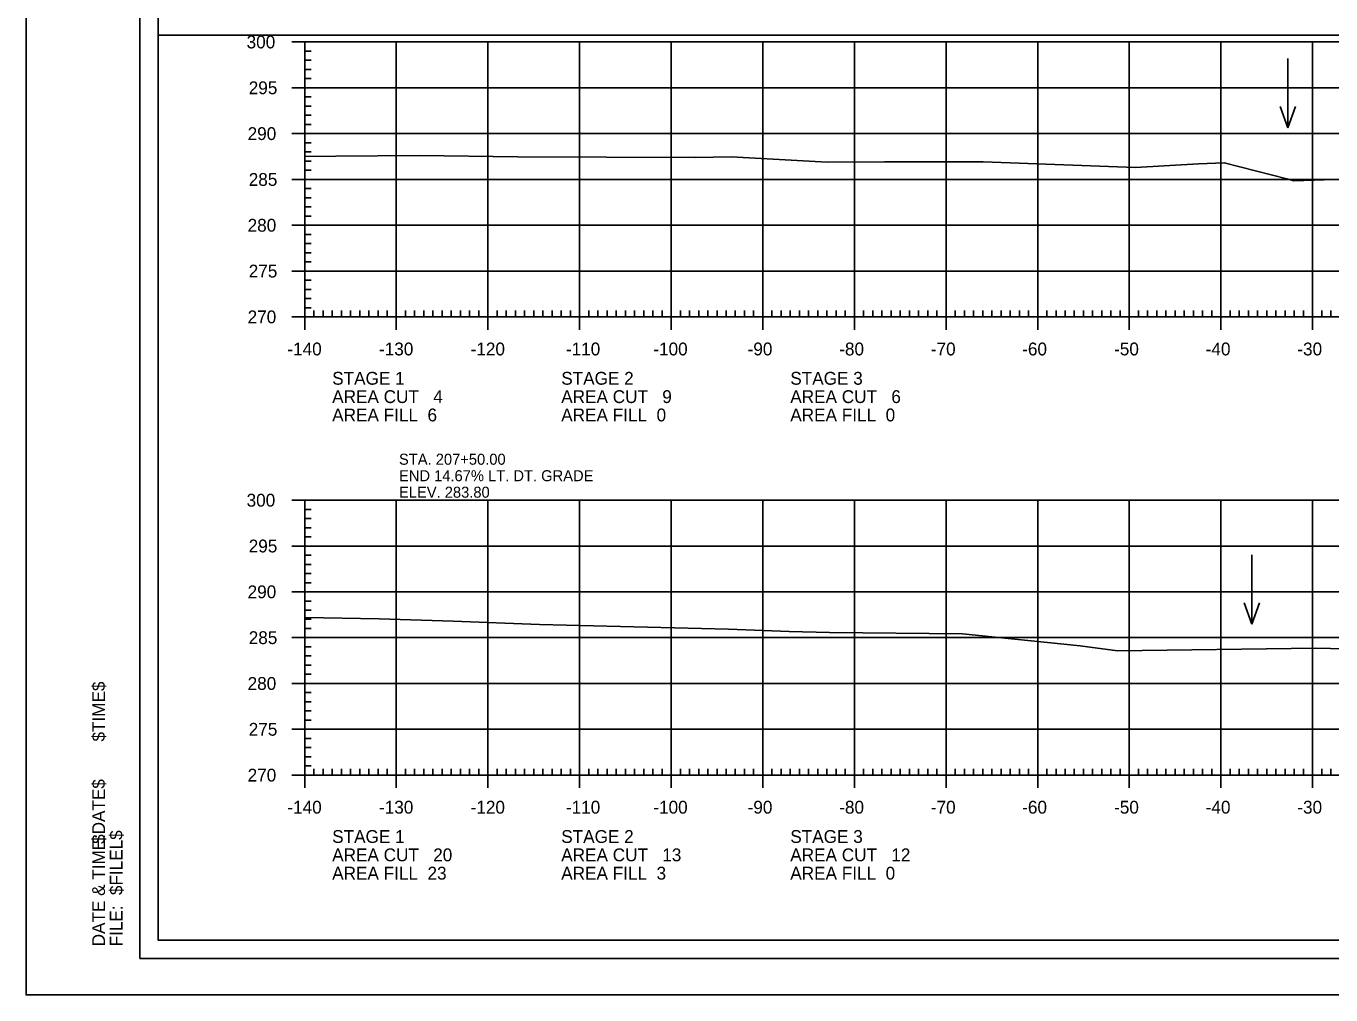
# Model space of a CAD drawing. Extents: x 1368713 to 1370673, y 380279 to 380950.
# Drawn here: x 1370339.2 to 1370481.6, y 380737.1 to 380842.8 of the extents above; entities that cross this region are included whole.
import ezdxf

# ---------------------------------------------------------------- set-up
doc = ezdxf.new("R2010")
doc.units = 0
for name, color, linetype in [('Notes', 7, 'Continuous'), ('R_Axis', 7, 'Continuous'), ('R_Axis Annot', 7, 'Continuous'), ('R_Border', 7, 'Continuous'), ('R_Border Notes', 7, 'Continuous'), ('R_Exist Surface', 7, 'Continuous'), ('R_Grid', 7, 'Continuous'), ('R_No Plot', 7, 'Continuous'), ('R_Water Annot', 7, 'Continuous')]:
    doc.layers.add(name, color=color, linetype=linetype)

msp = doc.modelspace()

# ---------------------------------------------------------------- linework, layer by layer
at = {"layer": 'R_Axis'}
for p, q in [((1370368.23, 380841.09), (1370371.03, 380841.09)), ((1370369.63, 380811.09), (1370369.63, 380841.09)), ((1370369.63, 380840.09), (1370370.33, 380840.09)), ((1370369.63, 380839.09), (1370370.33, 380839.09)), ((1370369.63, 380838.09), (1370370.33, 380838.09)), ((1370369.63, 380837.09), (1370370.33, 380837.09)), ((1370368.23, 380836.09), (1370371.03, 380836.09)), ((1370369.63, 380835.09), (1370370.33, 380835.09)), ((1370369.63, 380834.09), (1370370.33, 380834.09)), ((1370369.63, 380833.09), (1370370.33, 380833.09)), ((1370368.23, 380831.09), (1370371.03, 380831.09)), ((1370369.63, 380832.09), (1370370.33, 380832.09)), ((1370369.63, 380830.09), (1370370.33, 380830.09)), ((1370369.63, 380829.09), (1370370.33, 380829.09)), ((1370369.63, 380828.09), (1370370.33, 380828.09)), ((1370369.63, 380827.09), (1370370.33, 380827.09)), ((1370368.23, 380826.09), (1370371.03, 380826.09)), ((1370369.63, 380825.09), (1370370.33, 380825.09)), ((1370369.63, 380824.09), (1370370.33, 380824.09)), ((1370369.63, 380823.09), (1370370.33, 380823.09)), ((1370368.23, 380821.09), (1370371.03, 380821.09)), ((1370369.63, 380822.09), (1370370.33, 380822.09)), ((1370369.63, 380820.09), (1370370.33, 380820.09)), ((1370369.63, 380819.09), (1370370.33, 380819.09)), ((1370369.63, 380818.09), (1370370.33, 380818.09)), ((1370369.63, 380817.09), (1370370.33, 380817.09)), ((1370368.23, 380816.09), (1370371.03, 380816.09)), ((1370369.63, 380815.09), (1370370.33, 380815.09)), ((1370369.63, 380814.09), (1370370.33, 380814.09)), ((1370369.63, 380813.09), (1370370.33, 380813.09)), ((1370369.63, 380809.69), (1370369.63, 380812.49)), ((1370379.63, 380809.69), (1370379.63, 380812.49)), ((1370389.63, 380809.69), (1370389.63, 380812.49)), ((1370399.63, 380809.69), (1370399.63, 380812.49)), ((1370409.63, 380809.69), (1370409.63, 380812.49)), ((1370419.63, 380809.69), (1370419.63, 380812.49)), ((1370429.63, 380809.69), (1370429.63, 380812.49)), ((1370439.63, 380809.69), (1370439.63, 380812.49)), ((1370449.63, 380809.69), (1370449.63, 380812.49)), ((1370459.63, 380809.69), (1370459.63, 380812.49)), ((1370469.63, 380809.69), (1370469.63, 380812.49)), ((1370479.63, 380809.69), (1370479.63, 380812.49)), ((1370368.23, 380811.09), (1370371.03, 380811.09)), ((1370369.63, 380812.09), (1370370.33, 380812.09)), ((1370369.63, 380811.09), (1370649.63, 380811.09)), ((1370370.63, 380811.09), (1370370.63, 380811.79)), ((1370371.63, 380811.09), (1370371.63, 380811.79)), ((1370372.63, 380811.09), (1370372.63, 380811.79)), ((1370373.63, 380811.09), (1370373.63, 380811.79)), ((1370374.63, 380811.09), (1370374.63, 380811.79)), ((1370375.63, 380811.09), (1370375.63, 380811.79)), ((1370376.63, 380811.09), (1370376.63, 380811.79)), ((1370377.63, 380811.09), (1370377.63, 380811.79)), ((1370378.63, 380811.09), (1370378.63, 380811.79)), ((1370380.63, 380811.09), (1370380.63, 380811.79)), ((1370381.63, 380811.09), (1370381.63, 380811.79)), ((1370382.63, 380811.09), (1370382.63, 380811.79)), ((1370383.63, 380811.09), (1370383.63, 380811.79)), ((1370384.63, 380811.09), (1370384.63, 380811.79)), ((1370385.63, 380811.09), (1370385.63, 380811.79)), ((1370386.63, 380811.09), (1370386.63, 380811.79)), ((1370387.63, 380811.09), (1370387.63, 380811.79)), ((1370388.63, 380811.09), (1370388.63, 380811.79)), ((1370390.63, 380811.09), (1370390.63, 380811.79)), ((1370391.63, 380811.09), (1370391.63, 380811.79)), ((1370392.63, 380811.09), (1370392.63, 380811.79)), ((1370393.63, 380811.09), (1370393.63, 380811.79)), ((1370394.63, 380811.09), (1370394.63, 380811.79)), ((1370395.63, 380811.09), (1370395.63, 380811.79)), ((1370396.63, 380811.09), (1370396.63, 380811.79)), ((1370397.63, 380811.09), (1370397.63, 380811.79)), ((1370398.63, 380811.09), (1370398.63, 380811.79)), ((1370400.63, 380811.09), (1370400.63, 380811.79)), ((1370401.63, 380811.09), (1370401.63, 380811.79)), ((1370402.63, 380811.09), (1370402.63, 380811.79)), ((1370403.63, 380811.09), (1370403.63, 380811.79)), ((1370404.63, 380811.09), (1370404.63, 380811.79)), ((1370405.63, 380811.09), (1370405.63, 380811.79)), ((1370406.63, 380811.09), (1370406.63, 380811.79)), ((1370407.63, 380811.09), (1370407.63, 380811.79)), ((1370408.63, 380811.09), (1370408.63, 380811.79)), ((1370410.63, 380811.09), (1370410.63, 380811.79)), ((1370411.63, 380811.09), (1370411.63, 380811.79)), ((1370412.63, 380811.09), (1370412.63, 380811.79)), ((1370413.63, 380811.09), (1370413.63, 380811.79)), ((1370414.63, 380811.09), (1370414.63, 380811.79)), ((1370415.63, 380811.09), (1370415.63, 380811.79)), ((1370416.63, 380811.09), (1370416.63, 380811.79)), ((1370417.63, 380811.09), (1370417.63, 380811.79)), ((1370418.63, 380811.09), (1370418.63, 380811.79)), ((1370420.63, 380811.09), (1370420.63, 380811.79)), ((1370421.63, 380811.09), (1370421.63, 380811.79)), ((1370422.63, 380811.09), (1370422.63, 380811.79)), ((1370423.63, 380811.09), (1370423.63, 380811.79)), ((1370424.63, 380811.09), (1370424.63, 380811.79)), ((1370425.63, 380811.09), (1370425.63, 380811.79)), ((1370426.63, 380811.09), (1370426.63, 380811.79)), ((1370427.63, 380811.09), (1370427.63, 380811.79)), ((1370428.63, 380811.09), (1370428.63, 380811.79)), ((1370430.63, 380811.09), (1370430.63, 380811.79)), ((1370431.63, 380811.09), (1370431.63, 380811.79)), ((1370432.63, 380811.09), (1370432.63, 380811.79)), ((1370433.63, 380811.09), (1370433.63, 380811.79)), ((1370434.63, 380811.09), (1370434.63, 380811.79)), ((1370435.63, 380811.09), (1370435.63, 380811.79)), ((1370436.63, 380811.09), (1370436.63, 380811.79)), ((1370437.63, 380811.09), (1370437.63, 380811.79)), ((1370438.63, 380811.09), (1370438.63, 380811.79)), ((1370440.63, 380811.09), (1370440.63, 380811.79)), ((1370441.63, 380811.09), (1370441.63, 380811.79)), ((1370442.63, 380811.09), (1370442.63, 380811.79)), ((1370443.63, 380811.09), (1370443.63, 380811.79)), ((1370444.63, 380811.09), (1370444.63, 380811.79)), ((1370445.63, 380811.09), (1370445.63, 380811.79)), ((1370446.63, 380811.09), (1370446.63, 380811.79)), ((1370447.63, 380811.09), (1370447.63, 380811.79)), ((1370448.63, 380811.09), (1370448.63, 380811.79)), ((1370450.63, 380811.09), (1370450.63, 380811.79)), ((1370451.63, 380811.09), (1370451.63, 380811.79)), ((1370452.63, 380811.09), (1370452.63, 380811.79)), ((1370453.63, 380811.09), (1370453.63, 380811.79)), ((1370454.63, 380811.09), (1370454.63, 380811.79)), ((1370455.63, 380811.09), (1370455.63, 380811.79)), ((1370456.63, 380811.09), (1370456.63, 380811.79)), ((1370457.63, 380811.09), (1370457.63, 380811.79)), ((1370458.63, 380811.09), (1370458.63, 380811.79)), ((1370460.63, 380811.09), (1370460.63, 380811.79)), ((1370461.63, 380811.09), (1370461.63, 380811.79)), ((1370462.63, 380811.09), (1370462.63, 380811.79)), ((1370463.63, 380811.09), (1370463.63, 380811.79)), ((1370464.63, 380811.09), (1370464.63, 380811.79)), ((1370465.63, 380811.09), (1370465.63, 380811.79)), ((1370466.63, 380811.09), (1370466.63, 380811.79)), ((1370467.63, 380811.09), (1370467.63, 380811.79)), ((1370468.63, 380811.09), (1370468.63, 380811.79)), ((1370470.63, 380811.09), (1370470.63, 380811.79)), ((1370471.63, 380811.09), (1370471.63, 380811.79)), ((1370472.63, 380811.09), (1370472.63, 380811.79)), ((1370473.63, 380811.09), (1370473.63, 380811.79)), ((1370474.63, 380811.09), (1370474.63, 380811.79)), ((1370475.63, 380811.09), (1370475.63, 380811.79)), ((1370476.63, 380811.09), (1370476.63, 380811.79)), ((1370477.63, 380811.09), (1370477.63, 380811.79)), ((1370478.63, 380811.09), (1370478.63, 380811.79)), ((1370480.63, 380811.09), (1370480.63, 380811.79)), ((1370481.63, 380811.09), (1370481.63, 380811.79)), ((1370368.23, 380791.09), (1370371.03, 380791.09)), ((1370369.63, 380761.09), (1370369.63, 380791.09)), ((1370369.63, 380790.09), (1370370.33, 380790.09)), ((1370369.63, 380789.09), (1370370.33, 380789.09)), ((1370369.63, 380788.09), (1370370.33, 380788.09)), ((1370369.63, 380787.09), (1370370.33, 380787.09)), ((1370368.23, 380786.09), (1370371.03, 380786.09)), ((1370369.63, 380785.09), (1370370.33, 380785.09)), ((1370369.63, 380784.09), (1370370.33, 380784.09)), ((1370369.63, 380783.09), (1370370.33, 380783.09)), ((1370368.23, 380781.09), (1370371.03, 380781.09)), ((1370369.63, 380782.09), (1370370.33, 380782.09)), ((1370369.63, 380780.09), (1370370.33, 380780.09)), ((1370369.63, 380779.09), (1370370.33, 380779.09)), ((1370369.63, 380778.09), (1370370.33, 380778.09)), ((1370369.63, 380777.09), (1370370.33, 380777.09)), ((1370368.23, 380776.09), (1370371.03, 380776.09)), ((1370369.63, 380775.09), (1370370.33, 380775.09)), ((1370369.63, 380774.09), (1370370.33, 380774.09)), ((1370369.63, 380773.09), (1370370.33, 380773.09)), ((1370368.23, 380771.09), (1370371.03, 380771.09)), ((1370369.63, 380772.09), (1370370.33, 380772.09)), ((1370369.63, 380770.09), (1370370.33, 380770.09)), ((1370369.63, 380769.09), (1370370.33, 380769.09)), ((1370369.63, 380768.09), (1370370.33, 380768.09)), ((1370369.63, 380767.09), (1370370.33, 380767.09)), ((1370368.23, 380766.09), (1370371.03, 380766.09)), ((1370369.63, 380765.09), (1370370.33, 380765.09)), ((1370369.63, 380764.09), (1370370.33, 380764.09)), ((1370369.63, 380763.09), (1370370.33, 380763.09)), ((1370369.63, 380759.69), (1370369.63, 380762.49)), ((1370379.63, 380759.69), (1370379.63, 380762.49)), ((1370389.63, 380759.69), (1370389.63, 380762.49)), ((1370399.63, 380759.69), (1370399.63, 380762.49)), ((1370409.63, 380759.69), (1370409.63, 380762.49)), ((1370419.63, 380759.69), (1370419.63, 380762.49)), ((1370429.63, 380759.69), (1370429.63, 380762.49)), ((1370439.63, 380759.69), (1370439.63, 380762.49)), ((1370449.63, 380759.69), (1370449.63, 380762.49)), ((1370459.63, 380759.69), (1370459.63, 380762.49)), ((1370469.63, 380759.69), (1370469.63, 380762.49)), ((1370479.63, 380759.69), (1370479.63, 380762.49)), ((1370368.23, 380761.09), (1370371.03, 380761.09)), ((1370369.63, 380762.09), (1370370.33, 380762.09)), ((1370369.63, 380761.09), (1370649.63, 380761.09)), ((1370370.63, 380761.09), (1370370.63, 380761.79)), ((1370371.63, 380761.09), (1370371.63, 380761.79)), ((1370372.63, 380761.09), (1370372.63, 380761.79)), ((1370373.63, 380761.09), (1370373.63, 380761.79)), ((1370374.63, 380761.09), (1370374.63, 380761.79)), ((1370375.63, 380761.09), (1370375.63, 380761.79)), ((1370376.63, 380761.09), (1370376.63, 380761.79)), ((1370377.63, 380761.09), (1370377.63, 380761.79)), ((1370378.63, 380761.09), (1370378.63, 380761.79)), ((1370380.63, 380761.09), (1370380.63, 380761.79)), ((1370381.63, 380761.09), (1370381.63, 380761.79)), ((1370382.63, 380761.09), (1370382.63, 380761.79)), ((1370383.63, 380761.09), (1370383.63, 380761.79)), ((1370384.63, 380761.09), (1370384.63, 380761.79)), ((1370385.63, 380761.09), (1370385.63, 380761.79)), ((1370386.63, 380761.09), (1370386.63, 380761.79)), ((1370387.63, 380761.09), (1370387.63, 380761.79)), ((1370388.63, 380761.09), (1370388.63, 380761.79)), ((1370390.63, 380761.09), (1370390.63, 380761.79)), ((1370391.63, 380761.09), (1370391.63, 380761.79)), ((1370392.63, 380761.09), (1370392.63, 380761.79)), ((1370393.63, 380761.09), (1370393.63, 380761.79)), ((1370394.63, 380761.09), (1370394.63, 380761.79)), ((1370395.63, 380761.09), (1370395.63, 380761.79)), ((1370396.63, 380761.09), (1370396.63, 380761.79)), ((1370397.63, 380761.09), (1370397.63, 380761.79)), ((1370398.63, 380761.09), (1370398.63, 380761.79)), ((1370400.63, 380761.09), (1370400.63, 380761.79)), ((1370401.63, 380761.09), (1370401.63, 380761.79)), ((1370402.63, 380761.09), (1370402.63, 380761.79)), ((1370403.63, 380761.09), (1370403.63, 380761.79)), ((1370404.63, 380761.09), (1370404.63, 380761.79)), ((1370405.63, 380761.09), (1370405.63, 380761.79)), ((1370406.63, 380761.09), (1370406.63, 380761.79)), ((1370407.63, 380761.09), (1370407.63, 380761.79)), ((1370408.63, 380761.09), (1370408.63, 380761.79)), ((1370410.63, 380761.09), (1370410.63, 380761.79)), ((1370411.63, 380761.09), (1370411.63, 380761.79)), ((1370412.63, 380761.09), (1370412.63, 380761.79)), ((1370413.63, 380761.09), (1370413.63, 380761.79)), ((1370414.63, 380761.09), (1370414.63, 380761.79)), ((1370415.63, 380761.09), (1370415.63, 380761.79)), ((1370416.63, 380761.09), (1370416.63, 380761.79)), ((1370417.63, 380761.09), (1370417.63, 380761.79)), ((1370418.63, 380761.09), (1370418.63, 380761.79)), ((1370420.63, 380761.09), (1370420.63, 380761.79)), ((1370421.63, 380761.09), (1370421.63, 380761.79)), ((1370422.63, 380761.09), (1370422.63, 380761.79)), ((1370423.63, 380761.09), (1370423.63, 380761.79)), ((1370424.63, 380761.09), (1370424.63, 380761.79)), ((1370425.63, 380761.09), (1370425.63, 380761.79)), ((1370426.63, 380761.09), (1370426.63, 380761.79)), ((1370427.63, 380761.09), (1370427.63, 380761.79)), ((1370428.63, 380761.09), (1370428.63, 380761.79)), ((1370430.63, 380761.09), (1370430.63, 380761.79)), ((1370431.63, 380761.09), (1370431.63, 380761.79)), ((1370432.63, 380761.09), (1370432.63, 380761.79)), ((1370433.63, 380761.09), (1370433.63, 380761.79)), ((1370434.63, 380761.09), (1370434.63, 380761.79)), ((1370435.63, 380761.09), (1370435.63, 380761.79)), ((1370436.63, 380761.09), (1370436.63, 380761.79)), ((1370437.63, 380761.09), (1370437.63, 380761.79)), ((1370438.63, 380761.09), (1370438.63, 380761.79)), ((1370440.63, 380761.09), (1370440.63, 380761.79)), ((1370441.63, 380761.09), (1370441.63, 380761.79)), ((1370442.63, 380761.09), (1370442.63, 380761.79)), ((1370443.63, 380761.09), (1370443.63, 380761.79)), ((1370444.63, 380761.09), (1370444.63, 380761.79)), ((1370445.63, 380761.09), (1370445.63, 380761.79)), ((1370446.63, 380761.09), (1370446.63, 380761.79)), ((1370447.63, 380761.09), (1370447.63, 380761.79)), ((1370448.63, 380761.09), (1370448.63, 380761.79)), ((1370450.63, 380761.09), (1370450.63, 380761.79)), ((1370451.63, 380761.09), (1370451.63, 380761.79)), ((1370452.63, 380761.09), (1370452.63, 380761.79)), ((1370453.63, 380761.09), (1370453.63, 380761.79)), ((1370454.63, 380761.09), (1370454.63, 380761.79)), ((1370455.63, 380761.09), (1370455.63, 380761.79)), ((1370456.63, 380761.09), (1370456.63, 380761.79)), ((1370457.63, 380761.09), (1370457.63, 380761.79)), ((1370458.63, 380761.09), (1370458.63, 380761.79)), ((1370460.63, 380761.09), (1370460.63, 380761.79)), ((1370461.63, 380761.09), (1370461.63, 380761.79)), ((1370462.63, 380761.09), (1370462.63, 380761.79)), ((1370463.63, 380761.09), (1370463.63, 380761.79)), ((1370464.63, 380761.09), (1370464.63, 380761.79)), ((1370465.63, 380761.09), (1370465.63, 380761.79)), ((1370466.63, 380761.09), (1370466.63, 380761.79)), ((1370467.63, 380761.09), (1370467.63, 380761.79)), ((1370468.63, 380761.09), (1370468.63, 380761.79)), ((1370470.63, 380761.09), (1370470.63, 380761.79)), ((1370471.63, 380761.09), (1370471.63, 380761.79)), ((1370472.63, 380761.09), (1370472.63, 380761.79)), ((1370473.63, 380761.09), (1370473.63, 380761.79)), ((1370474.63, 380761.09), (1370474.63, 380761.79)), ((1370475.63, 380761.09), (1370475.63, 380761.79)), ((1370476.63, 380761.09), (1370476.63, 380761.79)), ((1370477.63, 380761.09), (1370477.63, 380761.79)), ((1370478.63, 380761.09), (1370478.63, 380761.79)), ((1370480.63, 380761.09), (1370480.63, 380761.79)), ((1370481.63, 380761.09), (1370481.63, 380761.79))]:
    msp.add_line(p, q, dxfattribs=at)
at = {"layer": 'R_Border'}
for p, q in [((1370351.63, 380741.09), (1370351.63, 380946.55)), ((1370351.63, 380741.09), (1370351.63, 380741.09)), ((1370667.81, 380741.09), (1370351.63, 380741.09))]:
    msp.add_line(p, q, dxfattribs=at)
at = {"layer": 'R_Exist Surface'}
for points in [[(1370369.63, 380828.58), (1370373.01, 380828.64), (1370382.16, 380828.69), (1370392.91, 380828.55), (1370412.23, 380828.48), (1370416.19, 380828.56), (1370426.65, 380827.99), (1370432.91, 380828.02), (1370443.68, 380828), (1370460.3, 380827.41), (1370467.17, 380827.8), (1370469.99, 380827.91), (1370476.84, 380826.16), (1370477.57, 380825.94), (1370483.13, 380826.11)], [(1370369.63, 380778.3), (1370377.76, 380778.14), (1370385.83, 380777.9), (1370395.25, 380777.53), (1370415.9, 380777), (1370422.49, 380776.78), (1370426.9, 380776.67), (1370441.42, 380776.51), (1370454.28, 380775.18), (1370458.35, 380774.65), (1370480, 380774.93), (1370483.18, 380774.88)]]:
    msp.add_lwpolyline(points, dxfattribs=at)
at = {"layer": 'R_Grid'}
for p, q in [((1370369.63, 380841.09), (1370649.63, 380841.09)), ((1370369.63, 380811.09), (1370369.63, 380841.09)), ((1370379.63, 380811.09), (1370379.63, 380841.09)), ((1370389.63, 380811.09), (1370389.63, 380841.09)), ((1370399.63, 380811.09), (1370399.63, 380841.09)), ((1370409.63, 380811.09), (1370409.63, 380841.09)), ((1370419.63, 380811.09), (1370419.63, 380841.09)), ((1370429.63, 380811.09), (1370429.63, 380841.09)), ((1370439.63, 380811.09), (1370439.63, 380841.09)), ((1370449.63, 380811.09), (1370449.63, 380841.09)), ((1370459.63, 380811.09), (1370459.63, 380841.09)), ((1370469.63, 380811.09), (1370469.63, 380841.09)), ((1370479.63, 380811.09), (1370479.63, 380841.09)), ((1370369.63, 380836.09), (1370649.63, 380836.09)), ((1370369.63, 380831.09), (1370649.63, 380831.09)), ((1370369.63, 380826.09), (1370649.63, 380826.09)), ((1370369.63, 380821.09), (1370649.63, 380821.09)), ((1370369.63, 380816.09), (1370649.63, 380816.09)), ((1370369.63, 380811.09), (1370649.63, 380811.09)), ((1370369.63, 380791.09), (1370649.63, 380791.09)), ((1370369.63, 380761.09), (1370369.63, 380791.09)), ((1370379.63, 380761.09), (1370379.63, 380791.09)), ((1370389.63, 380761.09), (1370389.63, 380791.09)), ((1370399.63, 380761.09), (1370399.63, 380791.09)), ((1370409.63, 380761.09), (1370409.63, 380791.09)), ((1370419.63, 380761.09), (1370419.63, 380791.09)), ((1370429.63, 380761.09), (1370429.63, 380791.09)), ((1370439.63, 380761.09), (1370439.63, 380791.09)), ((1370449.63, 380761.09), (1370449.63, 380791.09)), ((1370459.63, 380761.09), (1370459.63, 380791.09)), ((1370469.63, 380761.09), (1370469.63, 380791.09)), ((1370479.63, 380761.09), (1370479.63, 380791.09)), ((1370369.63, 380786.09), (1370649.63, 380786.09)), ((1370369.63, 380781.09), (1370649.63, 380781.09)), ((1370369.63, 380776.09), (1370649.63, 380776.09)), ((1370369.63, 380771.09), (1370649.63, 380771.09)), ((1370369.63, 380766.09), (1370649.63, 380766.09)), ((1370369.63, 380761.09), (1370649.63, 380761.09))]:
    msp.add_line(p, q, dxfattribs=at)
at = {"layer": 'R_No Plot'}
for points in [[(1370339.22, 380950.45), (1370672.56, 380950.45), (1370672.56, 380737.11), (1370339.22, 380737.11)], [(1370353.63, 380944.55), (1370603.17, 380944.55), (1370603.17, 380934.67), (1370620.71, 380934.67), (1370644.81, 380934.67), (1370644.81, 380912.34), (1370665.81, 380912.34), (1370665.81, 380743.09), (1370353.63, 380743.09)], [(1370353.63, 380841.82), (1370665.81, 380841.82), (1370665.81, 380743.09), (1370353.63, 380743.09)]]:
    msp.add_lwpolyline(points, close=True, dxfattribs=at)
at = {"layer": 'R_Water Annot'}
for p, q in [((1370476.94, 380839.27), (1370476.94, 380831.73)), ((1370476.94, 380831.73), (1370476.1, 380834.04)), ((1370476.94, 380831.73), (1370477.78, 380834.04)), ((1370473, 380785.12), (1370473, 380777.57)), ((1370473, 380777.57), (1370472.16, 380779.88)), ((1370473, 380777.57), (1370473.84, 380779.88))]:
    msp.add_line(p, q, dxfattribs=at)

# ---------------------------------------------------------------- texts
at = {"layer": 'Notes'}
for s, p in [('STA. 207+50.00', (1370379.92, 380794.96)), ('END 14.67% LT. DT. GRADE', (1370379.92, 380793.16)), ('ELEV. 283.80', (1370379.92, 380791.36))]:
    msp.add_text(s, height=1.2, dxfattribs=at).set_placement(p)
at = {"layer": 'R_Axis Annot'}
for s, p in [('300', (1370363.29, 380840.39)), ('295', (1370363.52, 380835.39)), ('290', (1370363.4, 380830.39)), ('285', (1370363.52, 380825.39)), ('280', (1370363.4, 380820.39)), ('275', (1370363.52, 380815.39)), ('270', (1370363.4, 380810.39)), ('-140', (1370367.74, 380806.89)), ('-130', (1370377.74, 380806.89)), ('-120', (1370387.74, 380806.89)), ('-110', (1370398.14, 380806.89)), ('-100', (1370407.68, 380806.89)), ('-90', (1370417.97, 380806.89)), ('-80', (1370427.97, 380806.89)), ('-70', (1370437.97, 380806.89)), ('-60', (1370447.94, 380806.89)), ('-50', (1370457.97, 380806.89)), ('-40', (1370467.97, 380806.89)), ('-30', (1370477.97, 380806.89)), ('STAGE 1', (1370372.63, 380803.69)), ('STAGE 2', (1370397.63, 380803.69)), ('STAGE 3', (1370422.63, 380803.69)), ('AREA CUT   4', (1370372.63, 380801.69)), ('AREA CUT   9', (1370397.63, 380801.69)), ('AREA CUT   6', (1370422.63, 380801.69)), ('AREA FILL  6', (1370372.63, 380799.69)), ('AREA FILL  0', (1370397.63, 380799.69)), ('AREA FILL  0', (1370422.63, 380799.69)), ('300', (1370363.29, 380790.39)), ('295', (1370363.52, 380785.39)), ('290', (1370363.4, 380780.39)), ('285', (1370363.52, 380775.39)), ('280', (1370363.4, 380770.39)), ('275', (1370363.52, 380765.39)), ('270', (1370363.4, 380760.39)), ('-140', (1370367.74, 380756.89)), ('-130', (1370377.74, 380756.89)), ('-120', (1370387.74, 380756.89)), ('-110', (1370398.14, 380756.89)), ('-100', (1370407.68, 380756.89)), ('-90', (1370417.97, 380756.89)), ('-80', (1370427.97, 380756.89)), ('-70', (1370437.97, 380756.89)), ('-60', (1370447.94, 380756.89)), ('-50', (1370457.97, 380756.89)), ('-40', (1370467.97, 380756.89)), ('-30', (1370477.97, 380756.89)), ('STAGE 1', (1370372.63, 380753.69)), ('STAGE 2', (1370397.63, 380753.69)), ('STAGE 3', (1370422.63, 380753.69)), ('AREA CUT   20', (1370372.63, 380751.69)), ('AREA CUT   13', (1370397.63, 380751.69)), ('AREA CUT   12', (1370422.63, 380751.69)), ('AREA FILL  23', (1370372.63, 380749.69)), ('AREA FILL  3', (1370397.63, 380749.69)), ('AREA FILL  0', (1370422.63, 380749.69))]:
    msp.add_text(s, height=1.4, dxfattribs=at).set_placement(p)
at = {"layer": 'R_Border Notes'}
for s, height, p in [('$TIME$', 1.397, (1370347.83, 380764.76)), ('$DATE$', 1.397, (1370347.83, 380753.59)), ('DATE & TIME:', 1.3968, (1370347.83, 380742.41)), ('$FILEL$', 1.397, (1370349.75, 380748)), ('FILE: ', 1.397, (1370349.75, 380742.41))]:
    msp.add_text(s, height=height, rotation=90, dxfattribs=at).set_placement(p)

doc.saveas('drawing.dxf')
